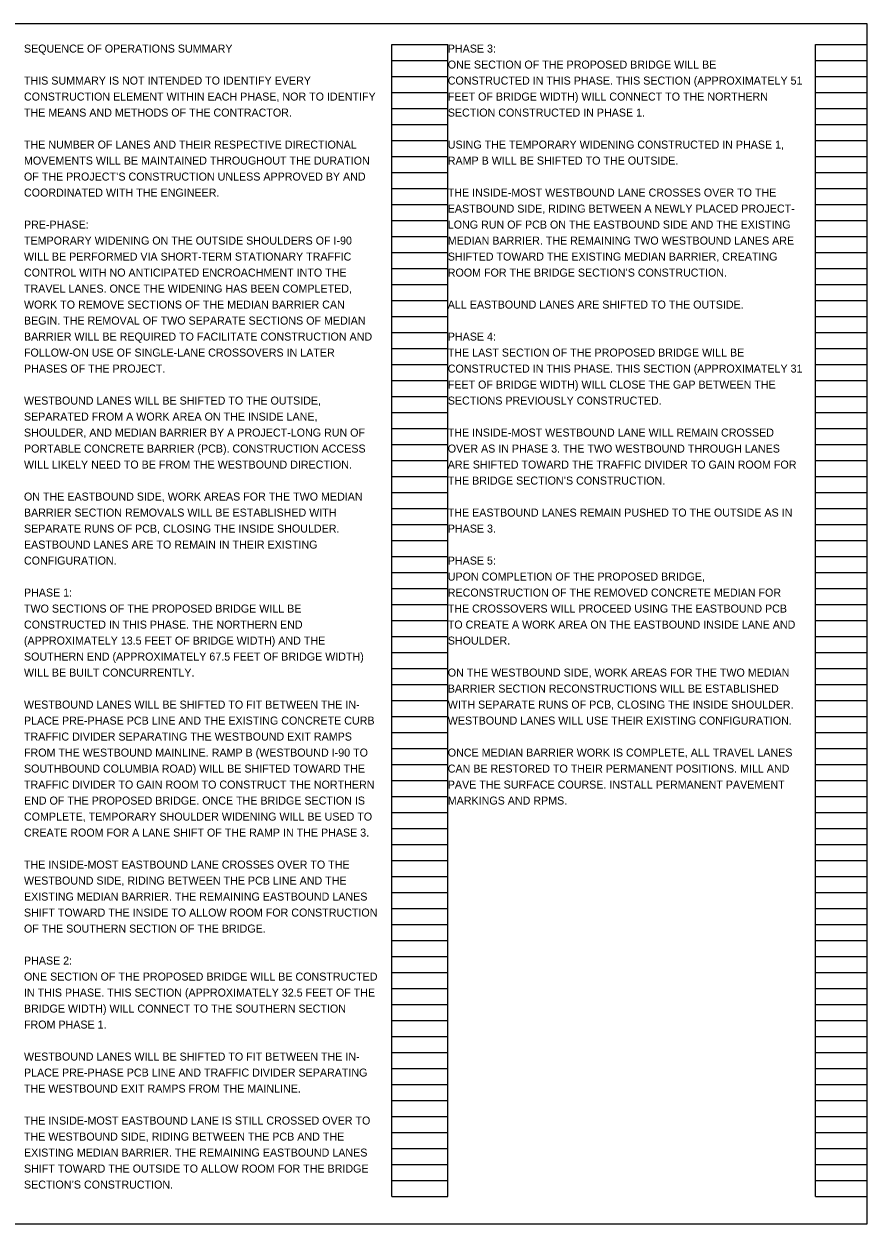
# Model space of a CAD drawing. Extents: x -34 to 2132911, y 0 to 658646.
# Drawn here: x 119.24 to 134, y 0.5 to 21.5 of the extents above; entities that cross this region are included whole.
import ezdxf

# ---------------------------------------------------------------- set-up
doc = ezdxf.new("R2010")
doc.units = 0
for name, color, linetype in [('SC_Scratch1', 7, 'Continuous'), ('SH_Data', 7, 'Continuous'), ('SH_Text', 7, 'Continuous')]:
    doc.layers.add(name, color=color, linetype=linetype)

msp = doc.modelspace()

# ---------------------------------------------------------------- linework, layer by layer
at = {"layer": 'SC_Scratch1'}
msp.add_lwpolyline([(103.5, 0.5), (134, 0.5), (134, 21.5), (103.5, 21.5)], close=True, dxfattribs=at)
at = {"layer": 'SH_Data'}
for p, q in [((125.68, 0.98), (125.68, 21.14)), ((125.68, 21.14), (126.66, 21.14)), ((126.66, 0.98), (126.66, 21.14)), ((133.1, 0.98), (133.1, 21.14)), ((133.1, 21.14), (134, 21.14)), ((134, 0.98), (134, 21.14)), ((125.68, 20.86), (126.66, 20.86)), ((133.1, 20.86), (134, 20.86)), ((125.68, 20.58), (126.66, 20.58)), ((133.1, 20.58), (134, 20.58)), ((125.68, 20.3), (126.66, 20.3)), ((133.1, 20.3), (134, 20.3)), ((125.68, 20.02), (126.66, 20.02)), ((133.1, 20.02), (134, 20.02)), ((125.68, 19.74), (126.66, 19.74)), ((133.1, 19.74), (134, 19.74)), ((125.68, 19.46), (126.66, 19.46)), ((133.1, 19.46), (134, 19.46)), ((125.68, 19.18), (126.66, 19.18)), ((133.1, 19.18), (134, 19.18)), ((125.68, 18.9), (126.66, 18.9)), ((133.1, 18.9), (134, 18.9)), ((125.68, 18.62), (126.66, 18.62)), ((133.1, 18.62), (134, 18.62)), ((125.68, 18.34), (126.66, 18.34)), ((133.1, 18.34), (134, 18.34)), ((125.68, 18.06), (126.66, 18.06)), ((133.1, 18.06), (134, 18.06)), ((125.68, 17.78), (126.66, 17.78)), ((133.1, 17.78), (134, 17.78)), ((125.68, 17.5), (126.66, 17.5)), ((133.1, 17.5), (134, 17.5)), ((125.68, 17.22), (126.66, 17.22)), ((133.1, 17.22), (134, 17.22)), ((125.68, 16.94), (126.66, 16.94)), ((133.1, 16.94), (134, 16.94)), ((125.68, 16.66), (126.66, 16.66)), ((133.1, 16.66), (134, 16.66)), ((125.68, 16.38), (126.66, 16.38)), ((133.1, 16.38), (134, 16.38)), ((125.68, 16.1), (126.66, 16.1)), ((133.1, 16.1), (134, 16.1)), ((125.68, 15.82), (126.66, 15.82)), ((133.1, 15.82), (134, 15.82)), ((125.68, 15.54), (126.66, 15.54)), ((133.1, 15.54), (134, 15.54)), ((125.68, 15.26), (126.66, 15.26)), ((133.1, 15.26), (134, 15.26)), ((125.68, 14.98), (126.66, 14.98)), ((133.1, 14.98), (134, 14.98)), ((125.68, 14.7), (126.66, 14.7)), ((133.1, 14.7), (134, 14.7)), ((125.68, 14.42), (126.66, 14.42)), ((133.1, 14.42), (134, 14.42)), ((125.68, 14.14), (126.66, 14.14)), ((133.1, 14.14), (134, 14.14)), ((125.68, 13.86), (126.66, 13.86)), ((133.1, 13.86), (134, 13.86)), ((125.68, 13.58), (126.66, 13.58)), ((133.1, 13.58), (134, 13.58)), ((125.68, 13.3), (126.66, 13.3)), ((133.1, 13.3), (134, 13.3)), ((125.68, 13.02), (126.66, 13.02)), ((133.1, 13.02), (134, 13.02)), ((125.68, 12.74), (126.66, 12.74)), ((133.1, 12.74), (134, 12.74)), ((125.68, 12.46), (126.66, 12.46)), ((133.1, 12.46), (134, 12.46)), ((125.68, 12.18), (126.66, 12.18)), ((133.1, 12.18), (134, 12.18)), ((125.68, 11.9), (126.66, 11.9)), ((133.1, 11.9), (134, 11.9)), ((125.68, 11.62), (126.66, 11.62)), ((133.1, 11.62), (134, 11.62)), ((125.68, 11.34), (126.66, 11.34)), ((133.1, 11.34), (134, 11.34)), ((125.68, 11.06), (126.66, 11.06)), ((133.1, 11.06), (134, 11.06)), ((125.68, 10.78), (126.66, 10.78)), ((133.1, 10.78), (134, 10.78)), ((125.68, 10.5), (126.66, 10.5)), ((133.1, 10.5), (134, 10.5)), ((125.68, 10.22), (126.66, 10.22)), ((133.1, 10.22), (134, 10.22)), ((125.68, 9.94), (126.66, 9.94)), ((133.1, 9.94), (134, 9.94)), ((125.68, 9.66), (126.66, 9.66)), ((133.1, 9.66), (134, 9.66)), ((125.68, 9.38), (126.66, 9.38)), ((133.1, 9.38), (134, 9.38)), ((125.68, 9.1), (126.66, 9.1)), ((133.1, 9.1), (134, 9.1)), ((125.68, 8.82), (126.66, 8.82)), ((133.1, 8.82), (134, 8.82)), ((125.68, 8.54), (126.66, 8.54)), ((133.1, 8.54), (134, 8.54)), ((125.68, 8.26), (126.66, 8.26)), ((133.1, 8.26), (134, 8.26)), ((125.68, 7.98), (126.66, 7.98)), ((133.1, 7.98), (134, 7.98)), ((125.68, 7.7), (126.66, 7.7)), ((133.1, 7.7), (134, 7.7)), ((125.68, 7.42), (126.66, 7.42)), ((133.1, 7.42), (134, 7.42)), ((125.68, 7.14), (126.66, 7.14)), ((133.1, 7.14), (134, 7.14)), ((125.68, 6.86), (126.66, 6.86)), ((133.1, 6.86), (134, 6.86)), ((125.68, 6.58), (126.66, 6.58)), ((133.1, 6.58), (134, 6.58)), ((125.68, 6.3), (126.66, 6.3)), ((133.1, 6.3), (134, 6.3)), ((125.68, 6.02), (126.66, 6.02)), ((133.1, 6.02), (134, 6.02)), ((125.68, 5.74), (126.66, 5.74)), ((133.1, 5.74), (134, 5.74)), ((125.68, 5.46), (126.66, 5.46)), ((133.1, 5.46), (134, 5.46)), ((125.68, 5.18), (126.66, 5.18)), ((133.1, 5.18), (134, 5.18)), ((125.68, 4.9), (126.66, 4.9)), ((133.1, 4.9), (134, 4.9)), ((125.68, 4.62), (126.66, 4.62)), ((133.1, 4.62), (134, 4.62)), ((125.68, 4.34), (126.66, 4.34)), ((133.1, 4.34), (134, 4.34)), ((125.68, 4.06), (126.66, 4.06)), ((133.1, 4.06), (134, 4.06)), ((125.68, 3.78), (126.66, 3.78)), ((133.1, 3.78), (134, 3.78)), ((125.68, 3.5), (126.66, 3.5)), ((133.1, 3.5), (134, 3.5)), ((125.68, 3.22), (126.66, 3.22)), ((133.1, 3.22), (134, 3.22)), ((125.68, 2.94), (126.66, 2.94)), ((133.1, 2.94), (134, 2.94)), ((125.68, 2.66), (126.66, 2.66)), ((133.1, 2.66), (134, 2.66)), ((125.68, 2.38), (126.66, 2.38)), ((133.1, 2.38), (134, 2.38)), ((125.68, 2.1), (126.66, 2.1)), ((133.1, 2.1), (134, 2.1)), ((125.68, 1.82), (126.66, 1.82)), ((133.1, 1.82), (134, 1.82)), ((125.68, 1.54), (126.66, 1.54)), ((133.1, 1.54), (134, 1.54)), ((125.68, 1.26), (126.66, 1.26)), ((133.1, 1.26), (134, 1.26)), ((125.68, 0.98), (126.66, 0.98)), ((133.1, 0.98), (134, 0.98))]:
    msp.add_line(p, q, dxfattribs=at)

# ---------------------------------------------------------------- texts
at = {"layer": 'SH_Text'}
for s, p in [('SEQUENCE OF OPERATIONS SUMMARY', (119.24, 21)), ('PHASE 3:', (126.66, 21)), ('ONE SECTION OF THE PROPOSED BRIDGE WILL BE ', (126.66, 20.72)), ('THIS SUMMARY IS NOT INTENDED TO IDENTIFY EVERY ', (119.24, 20.44)), ('CONSTRUCTED IN THIS PHASE. THIS SECTION (APPROXIMATELY 51 ', (126.66, 20.44)), ('CONSTRUCTION ELEMENT WITHIN EACH PHASE, NOR TO IDENTIFY ', (119.24, 20.16)), ('FEET OF BRIDGE WIDTH) WILL CONNECT TO THE NORTHERN ', (126.66, 20.16)), ('THE MEANS AND METHODS OF THE CONTRACTOR.', (119.24, 19.88)), ('SECTION CONSTRUCTED IN PHASE 1.', (126.66, 19.88)), ('THE NUMBER OF LANES AND THEIR RESPECTIVE DIRECTIONAL ', (119.24, 19.32)), ('USING THE TEMPORARY WIDENING CONSTRUCTED IN PHASE 1, ', (126.66, 19.32)), ('MOVEMENTS WILL BE MAINTAINED THROUGHOUT THE DURATION ', (119.24, 19.04)), ('RAMP B WILL BE SHIFTED TO THE OUTSIDE. ', (126.66, 19.04)), ('OF THE PROJECT’S CONSTRUCTION UNLESS APPROVED BY AND ', (119.24, 18.76)), ('COORDINATED WITH THE ENGINEER.', (119.24, 18.48)), ('THE INSIDE-MOST WESTBOUND LANE CROSSES OVER TO THE ', (126.66, 18.48)), ('EASTBOUND SIDE, RIDING BETWEEN A NEWLY PLACED PROJECT-', (126.66, 18.2)), ('PRE-PHASE:', (119.24, 17.92)), ('LONG RUN OF PCB ON THE EASTBOUND SIDE AND THE EXISTING ', (126.66, 17.92)), ('TEMPORARY WIDENING ON THE OUTSIDE SHOULDERS OF I-90 ', (119.24, 17.64)), ('MEDIAN BARRIER. THE REMAINING TWO WESTBOUND LANES ARE ', (126.66, 17.64)), ('WILL BE PERFORMED VIA SHORT-TERM STATIONARY TRAFFIC ', (119.24, 17.36)), ('SHIFTED TOWARD THE EXISTING MEDIAN BARRIER, CREATING ', (126.66, 17.36)), ('CONTROL WITH NO ANTICIPATED ENCROACHMENT INTO THE ', (119.24, 17.08)), ('ROOM FOR THE BRIDGE SECTION’S CONSTRUCTION.', (126.66, 17.08)), ('TRAVEL LANES. ONCE THE WIDENING HAS BEEN COMPLETED, ', (119.24, 16.8)), ('WORK TO REMOVE SECTIONS OF THE MEDIAN BARRIER CAN ', (119.24, 16.52)), ('ALL EASTBOUND LANES ARE SHIFTED TO THE OUTSIDE.', (126.66, 16.52)), ('BEGIN. THE REMOVAL OF TWO SEPARATE SECTIONS OF MEDIAN ', (119.24, 16.24)), ('BARRIER WILL BE REQUIRED TO FACILITATE CONSTRUCTION AND ', (119.24, 15.96)), ('PHASE 4:', (126.66, 15.96)), ('FOLLOW-ON USE OF SINGLE-LANE CROSSOVERS IN LATER ', (119.24, 15.68)), ('THE LAST SECTION OF THE PROPOSED BRIDGE WILL BE ', (126.66, 15.68)), ('PHASES OF THE PROJECT.', (119.24, 15.4)), ('CONSTRUCTED IN THIS PHASE. THIS SECTION (APPROXIMATELY 31 ', (126.66, 15.4)), ('FEET OF BRIDGE WIDTH) WILL CLOSE THE GAP BETWEEN THE ', (126.66, 15.12)), ('WESTBOUND LANES WILL BE SHIFTED TO THE OUTSIDE, ', (119.24, 14.84)), ('SECTIONS PREVIOUSLY CONSTRUCTED.', (126.66, 14.84)), ('SEPARATED FROM A WORK AREA ON THE INSIDE LANE, ', (119.24, 14.56)), ('SHOULDER, AND MEDIAN BARRIER BY A PROJECT-LONG RUN OF ', (119.24, 14.28)), ('THE INSIDE-MOST WESTBOUND LANE WILL REMAIN CROSSED ', (126.66, 14.28)), ('PORTABLE CONCRETE BARRIER (PCB). CONSTRUCTION ACCESS ', (119.24, 14)), ('OVER AS IN PHASE 3. THE TWO WESTBOUND THROUGH LANES ', (126.66, 14)), ('WILL LIKELY NEED TO BE FROM THE WESTBOUND DIRECTION. ', (119.24, 13.72)), ('ARE SHIFTED TOWARD THE TRAFFIC DIVIDER TO GAIN ROOM FOR ', (126.66, 13.72)), ('THE BRIDGE SECTION’S CONSTRUCTION.', (126.66, 13.44)), ('ON THE EASTBOUND SIDE, WORK AREAS FOR THE TWO MEDIAN ', (119.24, 13.16)), ('BARRIER SECTION REMOVALS WILL BE ESTABLISHED WITH ', (119.24, 12.88)), ('THE EASTBOUND LANES REMAIN PUSHED TO THE OUTSIDE AS IN ', (126.66, 12.88)), ('SEPARATE RUNS OF PCB, CLOSING THE INSIDE SHOULDER. ', (119.24, 12.6)), ('PHASE 3. ', (126.66, 12.6)), ('EASTBOUND LANES ARE TO REMAIN IN THEIR EXISTING ', (119.24, 12.32)), ('CONFIGURATION. ', (119.24, 12.04)), ('PHASE 5:', (126.66, 12.04)), ('UPON COMPLETION OF THE PROPOSED BRIDGE, ', (126.66, 11.76)), ('PHASE 1:', (119.24, 11.48)), ('RECONSTRUCTION OF THE REMOVED CONCRETE MEDIAN FOR ', (126.66, 11.48)), ('TWO SECTIONS OF THE PROPOSED BRIDGE WILL BE ', (119.24, 11.2)), ('THE CROSSOVERS WILL PROCEED USING THE EASTBOUND PCB ', (126.66, 11.2)), ('CONSTRUCTED IN THIS PHASE. THE NORTHERN END ', (119.24, 10.92)), ('TO CREATE A WORK AREA ON THE EASTBOUND INSIDE LANE AND ', (126.66, 10.92)), ('(APPROXIMATELY 13.5 FEET OF BRIDGE WIDTH) AND THE ', (119.24, 10.64)), ('SHOULDER. ', (126.66, 10.64)), ('SOUTHERN END (APPROXIMATELY 67.5 FEET OF BRIDGE WIDTH) ', (119.24, 10.36)), ('WILL BE BUILT CONCURRENTLY.', (119.24, 10.08)), ('ON THE WESTBOUND SIDE, WORK AREAS FOR THE TWO MEDIAN ', (126.66, 10.08)), ('BARRIER SECTION RECONSTRUCTIONS WILL BE ESTABLISHED ', (126.66, 9.8)), ('WESTBOUND LANES WILL BE SHIFTED TO FIT BETWEEN THE IN-', (119.24, 9.52)), ('WITH SEPARATE RUNS OF PCB, CLOSING THE INSIDE SHOULDER. ', (126.66, 9.52)), ('PLACE PRE-PHASE PCB LINE AND THE EXISTING CONCRETE CURB ', (119.24, 9.24)), ('WESTBOUND LANES WILL USE THEIR EXISTING CONFIGURATION. ', (126.66, 9.24)), ('TRAFFIC DIVIDER SEPARATING THE WESTBOUND EXIT RAMPS ', (119.24, 8.96)), ('FROM THE WESTBOUND MAINLINE. RAMP B (WESTBOUND I-90 TO ', (119.24, 8.68)), ('ONCE MEDIAN BARRIER WORK IS COMPLETE, ALL TRAVEL LANES ', (126.66, 8.68)), ('SOUTHBOUND COLUMBIA ROAD) WILL BE SHIFTED TOWARD THE ', (119.24, 8.4)), ('CAN BE RESTORED TO THEIR PERMANENT POSITIONS. MILL AND ', (126.66, 8.4)), ('TRAFFIC DIVIDER TO GAIN ROOM TO CONSTRUCT THE NORTHERN ', (119.24, 8.12)), ('PAVE THE SURFACE COURSE. INSTALL PERMANENT PAVEMENT ', (126.66, 8.12)), ('END OF THE PROPOSED BRIDGE. ONCE THE BRIDGE SECTION IS ', (119.24, 7.84)), ('MARKINGS AND RPMS.', (126.66, 7.84)), ('COMPLETE, TEMPORARY SHOULDER WIDENING WILL BE USED TO ', (119.24, 7.56)), ('CREATE ROOM FOR A LANE SHIFT OF THE RAMP IN THE PHASE 3.', (119.24, 7.28)), ('THE INSIDE-MOST EASTBOUND LANE CROSSES OVER TO THE ', (119.24, 6.72)), ('WESTBOUND SIDE, RIDING BETWEEN THE PCB LINE AND THE ', (119.24, 6.44)), ('EXISTING MEDIAN BARRIER. THE REMAINING EASTBOUND LANES ', (119.24, 6.16)), ('SHIFT TOWARD THE INSIDE TO ALLOW ROOM FOR CONSTRUCTION ', (119.24, 5.88)), ('OF THE SOUTHERN SECTION OF THE BRIDGE.  ', (119.24, 5.6)), ('PHASE 2:', (119.24, 5.04)), ('ONE SECTION OF THE PROPOSED BRIDGE WILL BE CONSTRUCTED ', (119.24, 4.76)), ('IN THIS PHASE. THIS SECTION (APPROXIMATELY 32.5 FEET OF THE ', (119.24, 4.48)), ('BRIDGE WIDTH) WILL CONNECT TO THE SOUTHERN SECTION ', (119.24, 4.2)), ('FROM PHASE 1.', (119.24, 3.92)), ('WESTBOUND LANES WILL BE SHIFTED TO FIT BETWEEN THE IN-', (119.24, 3.36)), ('PLACE PRE-PHASE PCB LINE AND TRAFFIC DIVIDER SEPARATING ', (119.24, 3.08)), ('THE WESTBOUND EXIT RAMPS FROM THE MAINLINE.', (119.24, 2.8)), ('THE INSIDE-MOST EASTBOUND LANE IS STILL CROSSED OVER TO ', (119.24, 2.24)), ('THE WESTBOUND SIDE, RIDING BETWEEN THE PCB AND THE ', (119.24, 1.96)), ('EXISTING MEDIAN BARRIER. THE REMAINING EASTBOUND LANES ', (119.24, 1.68)), ('SHIFT TOWARD THE OUTSIDE TO ALLOW ROOM FOR THE BRIDGE ', (119.24, 1.4)), ('SECTION’S CONSTRUCTION.', (119.24, 1.12))]:
    msp.add_text(s, height=0.14, dxfattribs=at).set_placement(p)

doc.saveas('drawing.dxf')
